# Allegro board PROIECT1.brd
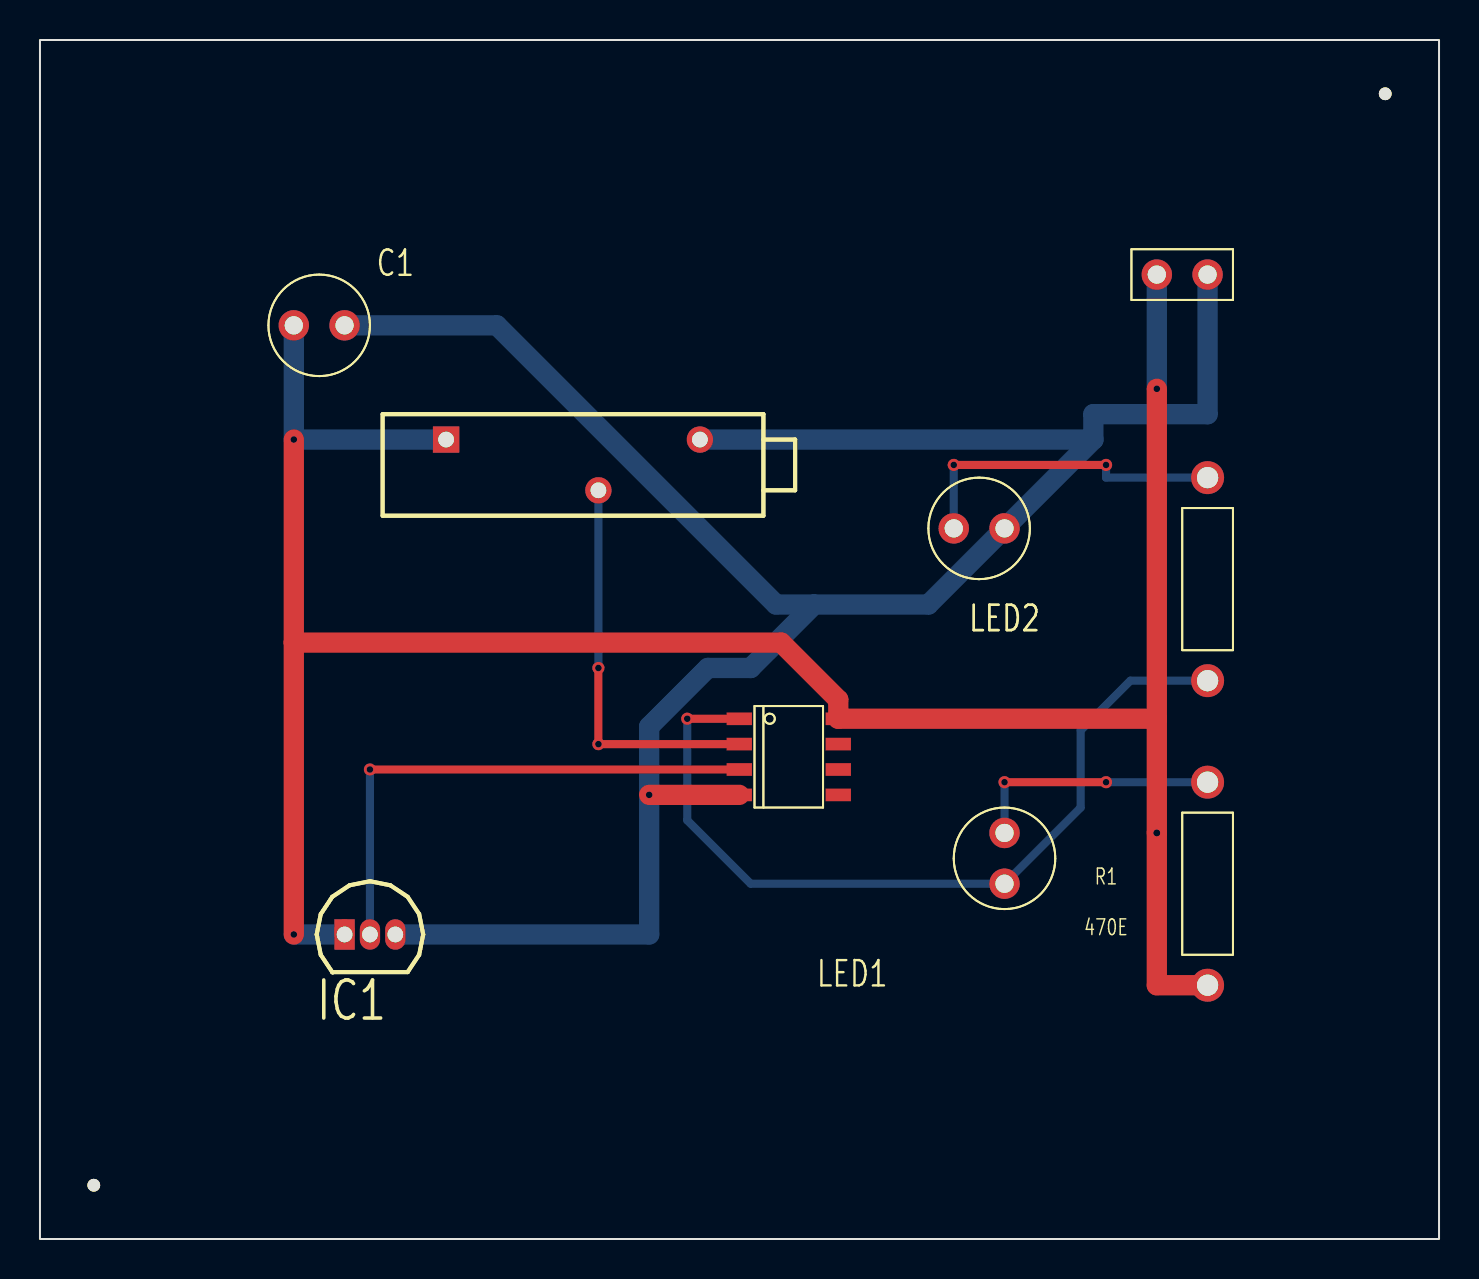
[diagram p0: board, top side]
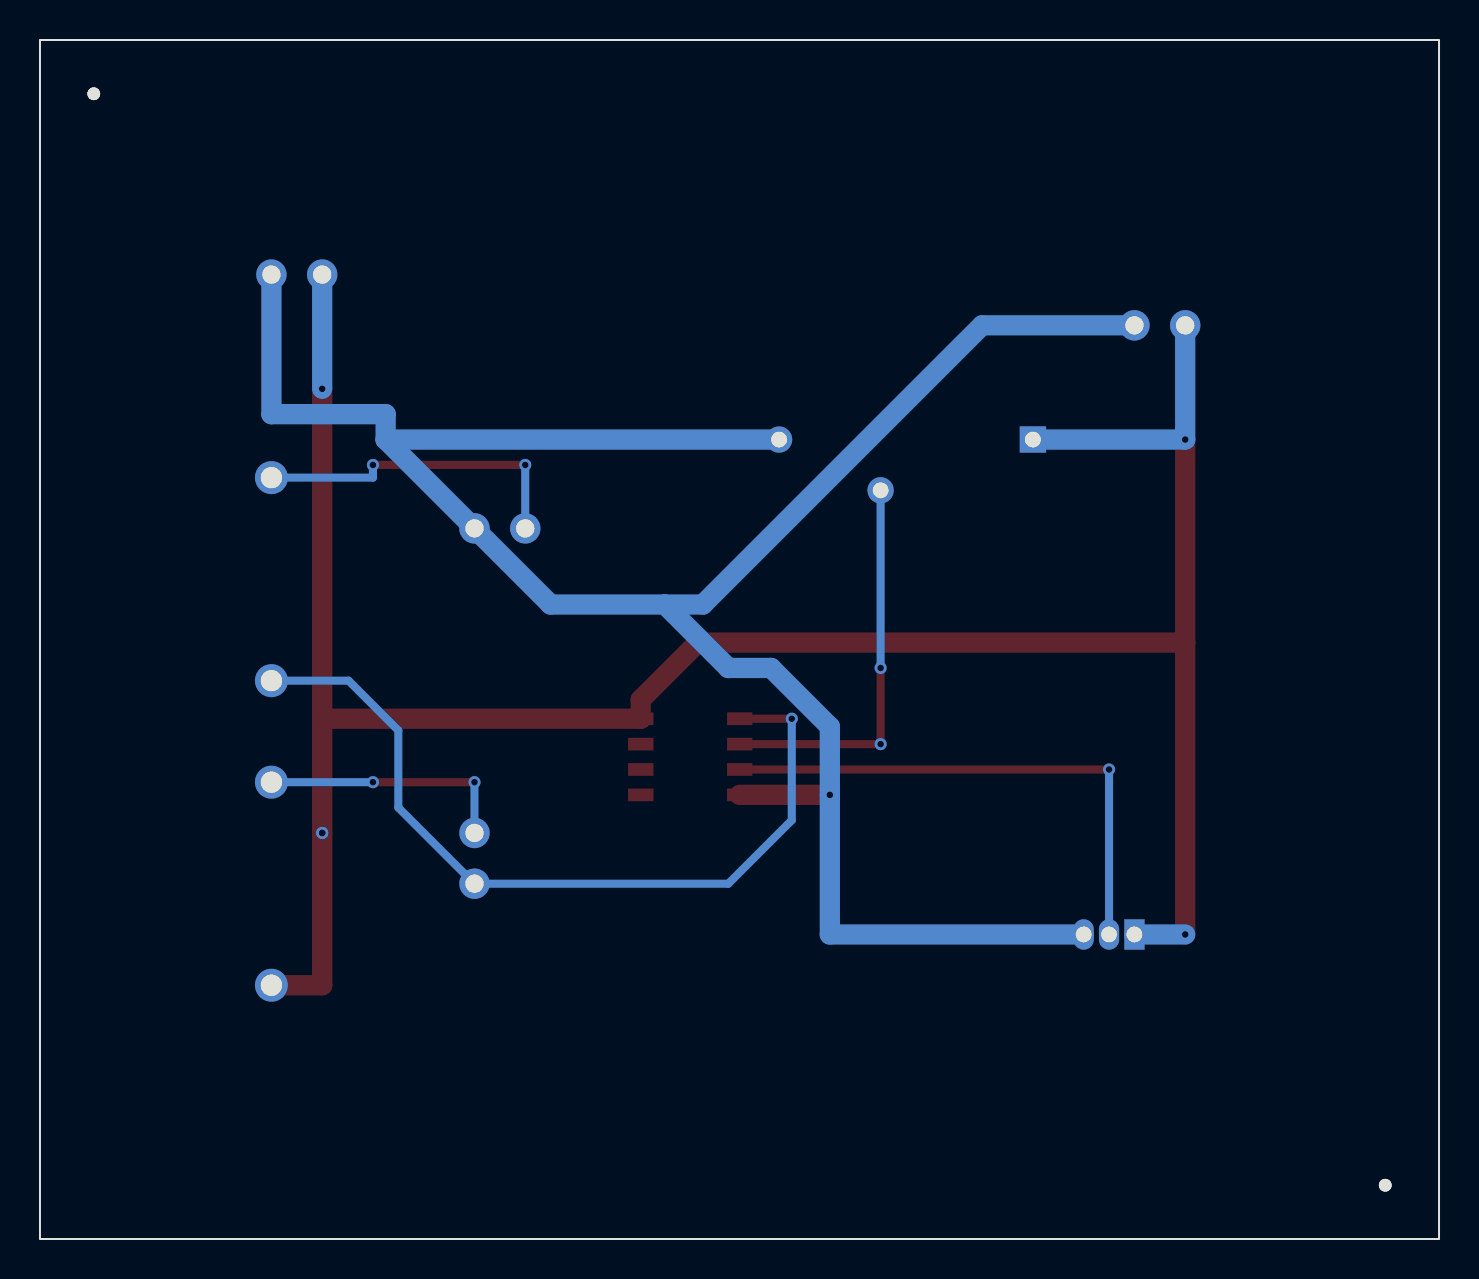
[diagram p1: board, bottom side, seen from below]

Outline 70 x 60 mm; copper layers: TOP, BOTTOM. Coordinates in mm from the lower left corner of the outline.
Outline path: rectangle 0,0 70,60

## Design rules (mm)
nets with their own width: min track width 0.406; nets N00529 N00677 N00684 N00778 N03337
nets with their own width: min track width 1.016; nets +5V GND

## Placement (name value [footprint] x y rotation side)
C1  100uF  [CAP196]  12.7 45.72 270 top
IC1  LM35  [TO92]  15.24 15.24 0 top
J1  CON2  [JUMPER2]  55.88 48.26 0 top
LED1  RED LED  [CAP196]  48.26 20.32 180 top
LED2  GREEN LED  [CAP196]  45.72 35.56 270 top
NOREF  -  [unnamed]  2.69 2.69 0 top
NOREF#2  -  [unnamed]  67.31 57.31 0 top
R1  470E  [RES400]  58.42 12.7 0 top
R2  470E  [RES400]  58.42 27.94 0 top
U1G1  LM358  [SOIC8]  37.47 24.13 0 top
VR1  10k  [VRES9]  20.32 40.01 180 top

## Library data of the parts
C1 = CAP POL
IC1 = LM35/SO_10
J1 = CON2: User Part Number: ***
LED1 LED2 = LED
R1 R2 = R
U1G1 = LM358
VR1 = POT

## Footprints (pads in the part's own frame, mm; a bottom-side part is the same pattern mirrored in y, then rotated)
CAP196
  round 1.524 hole 0.914: 1(0,0) 2(0,2.54)
JUMPER2
  round 1.524 hole 0.914: 1(0,0) 2(2.54,0)
RES400
  round 1.651 hole 1.067: 1(0,0) 2(0,10.16)
SOIC8
  rect 1.27x0.635 smd: 1(-2.477,1.905) 2(-2.477,0.635) 3(-2.477,-0.635) 4(-2.477,-1.905) 5(2.477,-1.905) 6(2.477,-0.635) 7(2.477,0.635) 8(2.477,1.905)
TO92
  rect 1.016x1.524 hole 0.787: 1(0,0)
  oval 1.016x1.524 hole 0.787: 2(1.27,0) 3(2.54,0)
unnamed
  round 0.635 hole 3.175 unplated: (0,0)
VRES9
  rect 1.321x1.321 hole 0.787: 1(0,0)
  round 1.321 hole 0.787: 2(-7.62,2.54) 3(-12.7,0)

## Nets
+5V: C1.1 IC1.1 J1.1 R1.1 U1G1.8 VR1.1
GND: C1.2 IC1.3 J1.2 LED2.2(CATHODE) U1G1.4 VR1.3
N00529: LED2.1 R2.2
N00677: U1G1.2 VR1.2(WIPER)
N00684: IC1.2(VO) U1G1.3
N00778: LED1.2(CATHODE) R2.1 U1G1.1
N03337: LED1.1 R1.2

Pads without a net: U1G1 5 6 7

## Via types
v1: diameter 0.61, hole 0.33, TOP to BOTTOM, 15 vias

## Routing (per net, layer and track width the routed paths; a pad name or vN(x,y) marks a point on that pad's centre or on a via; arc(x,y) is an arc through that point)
+5V: length 124.3
  TOP w1.016: v1(12.7,40.01) 12.7,29.84 ; 12.7,29.84 v1(12.7,15.24) ; 12.7,29.84 37.08,29.84 39.94,26.99 U1G1.8 55.88,26.04 ; 55.88,26.04 v1(55.88,20.32) 55.88,12.7 R1.1 ; 55.88,26.04 v1(55.88,42.55) ; IC1.1 15.24,15.49
  BOTTOM w1.016: C1.1 v1(12.7,40.01) VR1.1 ; J1.1 v1(55.88,42.55) ; IC1.1 v1(12.7,15.24)
GND: length 118.7
  TOP w1.016: U1G1.4 v1(30.48,22.23)
  BOTTOM w1.016: J1.2 58.42,41.27 52.7,41.27 52.7,40.01 ; 38.73,31.75 35.56,28.57 33.42,28.57 30.48,25.64 v1(30.48,22.23) 30.48,15.24 IC1.3 ; 38.73,31.75 44.45,31.75 LED2.2 52.7,40.01 ; 38.73,31.75 36.83,31.75 22.86,45.72 C1.2 ; VR1.3 52.7,40.01
N00529: length 16.5
  TOP w0.406: v1(53.34,38.73) v1(45.72,38.73)
  BOTTOM w0.406: R2.2 53.34,38.1 v1(53.34,38.73) ; v1(45.72,38.73) LED2.1
N00677: length 19.7
  TOP w0.406: U1G1.2 v1(27.94,24.77) v1(27.94,28.57)
  BOTTOM w0.406: VR1.2 v1(27.94,28.57)
N00684: length 26.7
  TOP w0.406: 34.99,23.5 v1(16.51,23.5)
  BOTTOM w0.406: v1(16.51,23.5) IC1.2
N00778: length 41.5
  TOP w0.406: U1G1.1 v1(32.38,26.04)
  BOTTOM w0.406: v1(32.38,26.04) 32.38,20.95 35.56,17.78 LED1.2 52.07,21.59 52.07,25.45 54.56,27.94 R2.1
N03337: length 12.7
  TOP w0.406: v1(53.34,22.86) v1(48.26,22.86)
  BOTTOM w0.406: v1(58.42,22.86) v1(53.34,22.86) ; v1(48.26,22.86) LED1.1
